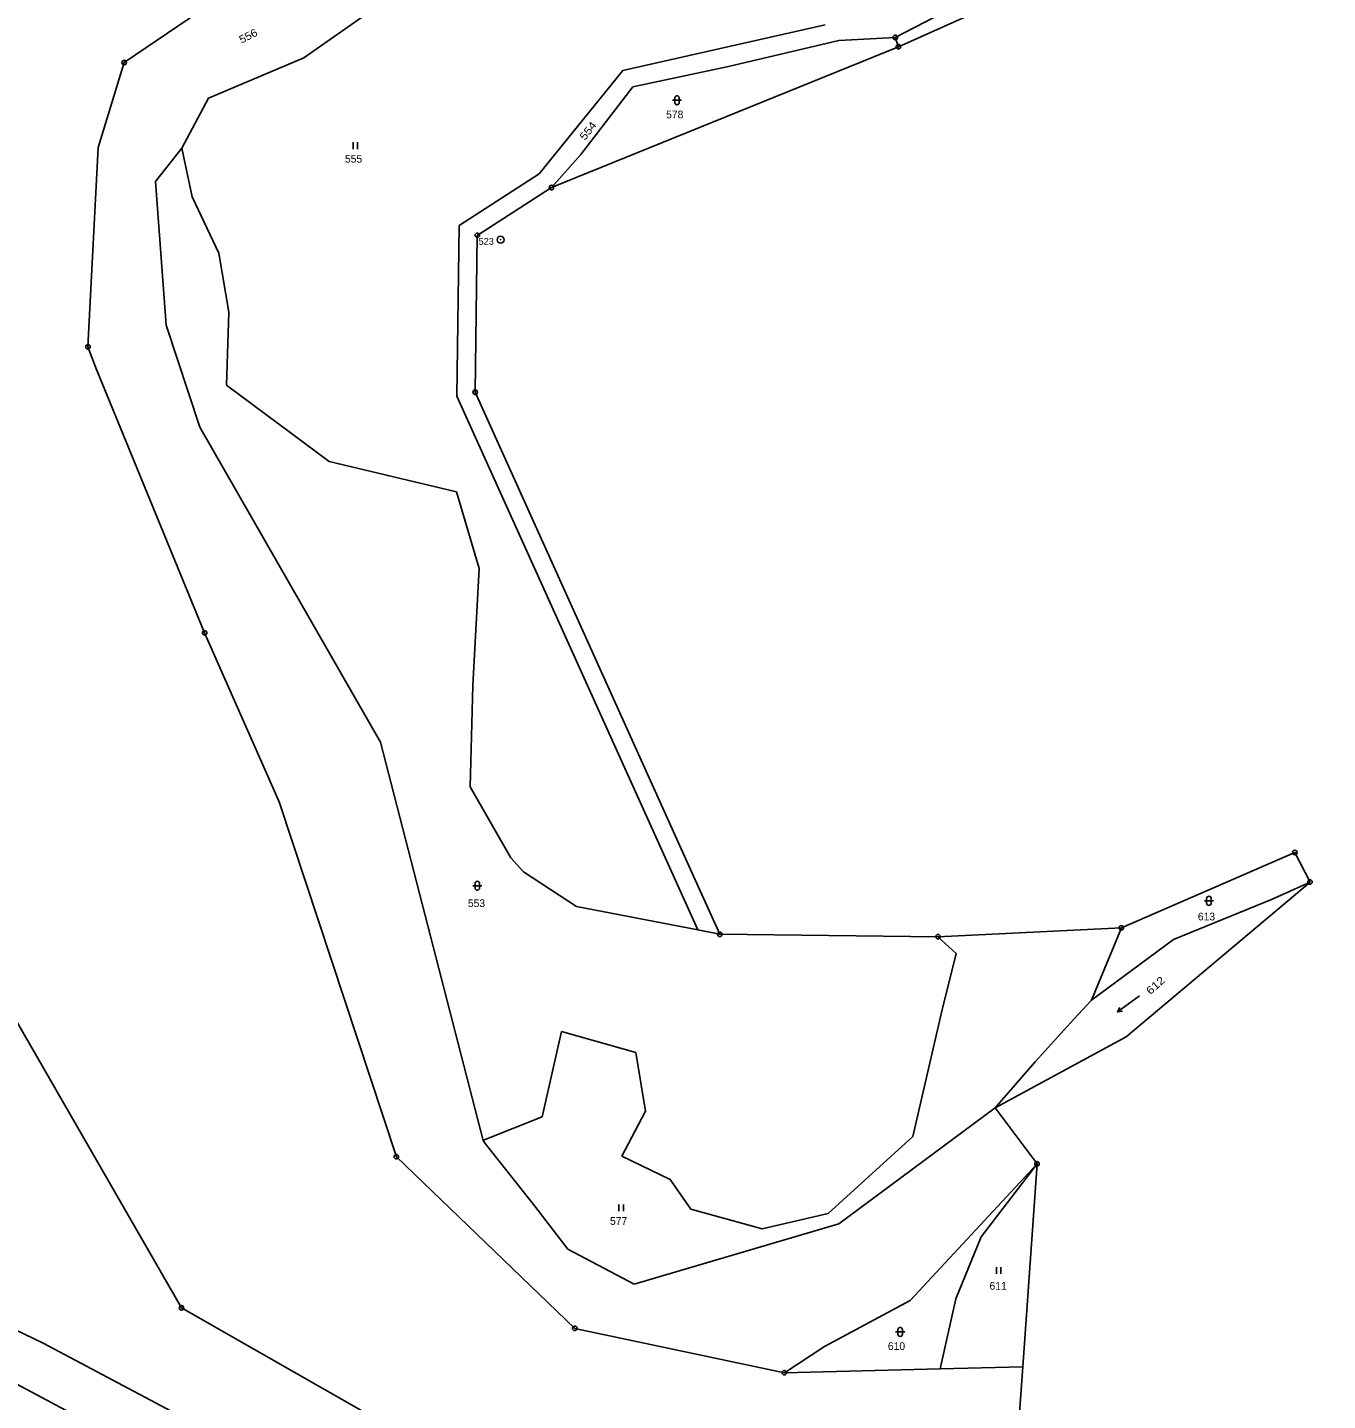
# Model space of a CAD drawing. Extents: x -719614 to -717765, y -1095834 to -1093862.
# Drawn here: x -718549.9 to -718263.5, y -1095573 to -1095270.4 of the extents above; entities that cross this region are included whole.
import ezdxf
from ezdxf.enums import TextEntityAlignment as Align

# ---------------------------------------------------------------- set-up
doc = ezdxf.new("R2010")
doc.units = 0
doc.header["$LTSCALE"] = 0.68
for name, color, linetype, lineweight in [('1', 7, 'Continuous', 25), ('3', 7, 'Continuous', 25), ('8', 7, 'Continuous', 25)]:
    doc.layers.add(name, color=color, linetype=linetype, lineweight=lineweight)
doc.layers.add('2', color=7, linetype='Continuous')

msp = doc.modelspace()

# ---------------------------------------------------------------- linework, layer by layer
at = {"layer": '1'}
for p, q in [((-718358.01, -1095274.64), (-718206.61, -1095206.83)), ((-718528.56, -1095278.15), (-718474.41, -1095241.35)), ((-718358.69, -1095272.6), (-718305.66, -1095245.1)), ((-718472.63, -1095265.67), (-718489.02, -1095277.08)), ((-718418.73, -1095279.86), (-718374.13, -1095269.82)), ((-718371.16, -1095273.26), (-718395.43, -1095279.04)), ((-718358.69, -1095272.6), (-718371.16, -1095273.26)), ((-718358.01, -1095274.64), (-718358.69, -1095272.6)), ((-718489.02, -1095277.08), (-718509.98, -1095286)), ((-718434.44, -1095305.7), (-718358.01, -1095274.64)), ((-718534.28, -1095296.85), (-718528.56, -1095278.15)), ((-718437.15, -1095302.69), (-718418.73, -1095279.86)), ((-718395.43, -1095279.04), (-718416.51, -1095283.48)), ((-718509.98, -1095286), (-718515.85, -1095297.01)), ((-718416.51, -1095283.48), (-718427.97, -1095298.42)), ((-718536.55, -1095340.82), (-718534.28, -1095296.85)), ((-718515.85, -1095297.01), (-718521.65, -1095304.39)), ((-718513.57, -1095307.72), (-718515.85, -1095297.01)), ((-718427.97, -1095298.42), (-718434.44, -1095305.7)), ((-718521.65, -1095304.39), (-718519.35, -1095336.03)), ((-718454.75, -1095314.03), (-718437.15, -1095302.69)), ((-718450.78, -1095316.23), (-718434.44, -1095305.7)), ((-718507.71, -1095320.18), (-718513.57, -1095307.72)), ((-718455.26, -1095351.64), (-718454.75, -1095314.03)), ((-718451.25, -1095350.81), (-718450.78, -1095316.23)), ((-718505.54, -1095333.16), (-718507.71, -1095320.18)), ((-718506.05, -1095349.28), (-718505.54, -1095333.16)), ((-718519.35, -1095336.03), (-718511.88, -1095358.48)), ((-718534.69, -1095345.76), (-718536.55, -1095340.82)), ((-718510.85, -1095403.84), (-718534.69, -1095345.76)), ((-718483.41, -1095366.04), (-718506.05, -1095349.28)), ((-718402.18, -1095469.27), (-718455.26, -1095351.64)), ((-718402.78, -1095458.27), (-718451.25, -1095350.81)), ((-718511.88, -1095358.48), (-718472.08, -1095427.94)), ((-718455.35, -1095372.74), (-718483.41, -1095366.04)), ((-718450.38, -1095389.64), (-718455.35, -1095372.74)), ((-718451.78, -1095415.45), (-718450.38, -1095389.64)), ((-718494.44, -1095441.1), (-718510.85, -1095403.84)), ((-718452.36, -1095437.8), (-718451.78, -1095415.45)), ((-718472.08, -1095427.94), (-718449.52, -1095515.72)), ((-718443.36, -1095453.44), (-718452.36, -1095437.8)), ((-718468.61, -1095519.3), (-718494.44, -1095441.1)), ((-718270.67, -1095452.26), (-718308.89, -1095468.86)), ((-718267.32, -1095458.76), (-718270.67, -1095452.26)), ((-718440.59, -1095456.48), (-718443.36, -1095453.44)), ((-718428.92, -1095464.17), (-718440.59, -1095456.48)), ((-718397.36, -1095470.29), (-718402.78, -1095458.27)), ((-718307.81, -1095492.88), (-718267.32, -1095458.76)), ((-718267.32, -1095458.76), (-718275.79, -1095462.62)), ((-718402.18, -1095469.27), (-718428.92, -1095464.17)), ((-718275.79, -1095462.62), (-718297.38, -1095471.45)), ((-718397.36, -1095470.29), (-718402.18, -1095469.27)), ((-718349.29, -1095470.82), (-718397.36, -1095470.29)), ((-718308.89, -1095468.86), (-718349.29, -1095470.82)), ((-718349.29, -1095470.82), (-718345.32, -1095474.48)), ((-718315.49, -1095484.77), (-718308.89, -1095468.86)), ((-718297.38, -1095471.45), (-718315.49, -1095484.77)), ((-718345.32, -1095474.48), (-718348.49, -1095487.54)), ((-718515.95, -1095552.63), (-718555.1, -1095484.57)), ((-718315.49, -1095484.77), (-718319.34, -1095489)), ((-718348.49, -1095487.54), (-718354.86, -1095514.83)), ((-718319.34, -1095489), (-718327.85, -1095498.37)), ((-718432.25, -1095491.71), (-718436.51, -1095510.5)), ((-718415.87, -1095496.37), (-718432.25, -1095491.71)), ((-718413.74, -1095509.3), (-718415.87, -1095496.37)), ((-718327.85, -1095498.37), (-718336.67, -1095508.55)), ((-718418.93, -1095519.15), (-718413.74, -1095509.3)), ((-718371.15, -1095534.11), (-718336.67, -1095508.55)), ((-718436.51, -1095510.5), (-718449.01, -1095515.52)), ((-718449.01, -1095515.52), (-718449.52, -1095515.72)), ((-718449.52, -1095515.72), (-718449.01, -1095516.43)), ((-718354.86, -1095514.83), (-718373.47, -1095531.84)), ((-718429.31, -1095557.14), (-718468.61, -1095519.3)), ((-718449.01, -1095516.43), (-718438.12, -1095530.19)), ((-718408.28, -1095524.33), (-718418.93, -1095519.15)), ((-718327.47, -1095520.86), (-718355.39, -1095551.01)), ((-718339.76, -1095536.99), (-718327.47, -1095520.86)), ((-718330.61, -1095565.64), (-718327.47, -1095520.86)), ((-718403.75, -1095530.89), (-718408.28, -1095524.33)), ((-718438.12, -1095530.19), (-718430.8, -1095539.71)), ((-718388, -1095535.17), (-718403.75, -1095530.89)), ((-718416.2, -1095547.38), (-718371.15, -1095534.11)), ((-718373.47, -1095531.84), (-718388, -1095535.17)), ((-718345.37, -1095550.63), (-718339.76, -1095536.99)), ((-718430.8, -1095539.71), (-718416.2, -1095547.38)), ((-718578.93, -1095544.76), (-718546.41, -1095560.42)), ((-718453.18, -1095588.42), (-718515.95, -1095552.63)), ((-718355.39, -1095551.01), (-718374.3, -1095561.14)), ((-718348.84, -1095566.09), (-718345.37, -1095550.63)), ((-718383.13, -1095566.91), (-718429.31, -1095557.14)), ((-718492.07, -1095601.38), (-718570.21, -1095559.91)), ((-718546.41, -1095560.42), (-718505.05, -1095582.36)), ((-718374.3, -1095561.14), (-718383.13, -1095566.91)), ((-718383.13, -1095566.91), (-718348.84, -1095566.09)), ((-718348.84, -1095566.09), (-718330.61, -1095565.64)), ((-718331.65, -1095580.47), (-718330.61, -1095565.64))]:
    msp.add_line(p, q, dxfattribs=at)
msp.add_lwpolyline([(-718327.47, -1095520.86), (-718336.67, -1095508.55), (-718307.81, -1095492.88)], dxfattribs=at)
at = {"layer": '3'}
for p, q in [((-718407.291, -1095285.951), (-718407.291, -1095286.952)), ((-718406.289, -1095286.952), (-718406.289, -1095285.951)), ((-718407.791, -1095286.451), (-718405.789, -1095286.451)), ((-718478.151, -1095297.22), (-718478.151, -1095295.72)), ((-718477.15, -1095297.22), (-718477.15, -1095295.72)), ((-718451.761, -1095459.571), (-718449.759, -1095459.571)), ((-718451.261, -1095459.071), (-718451.261, -1095460.072)), ((-718450.259, -1095460.072), (-718450.259, -1095459.071)), ((-718290.601, -1095462.911), (-718288.599, -1095462.911)), ((-718290.101, -1095462.411), (-718290.101, -1095463.412)), ((-718289.099, -1095463.412), (-718289.099, -1095462.411)), ((-718309.746, -1095487.376), (-718309.25, -1095486.396)), ((-718419.601, -1095531.34), (-718419.601, -1095529.84)), ((-718418.6, -1095531.34), (-718418.6, -1095529.84)), ((-718336.421, -1095545.15), (-718336.421, -1095543.65)), ((-718335.42, -1095545.15), (-718335.42, -1095543.65)), ((-718358.621, -1095557.921), (-718356.619, -1095557.921)), ((-718358.121, -1095557.421), (-718358.121, -1095558.422)), ((-718357.119, -1095558.422), (-718357.119, -1095557.421))]:
    msp.add_line(p, q, dxfattribs=at)
msp.add_lwpolyline([(-718304.892, -1095483.85), (-718309.746, -1095487.376), (-718308.661, -1095487.208)], dxfattribs=at)
for centre, start, end in [((-718406.79, -1095285.9509), 0, 180), ((-718406.79, -1095286.9509), 180, 359.98789), ((-718450.76, -1095459.0709), 0, 180), ((-718450.76, -1095460.0709), 180, 359.98789), ((-718289.6, -1095462.4109), 0, 180), ((-718289.6, -1095463.4109), 180, 359.98789), ((-718357.62, -1095557.4209), 0, 180), ((-718357.62, -1095558.4209), 180, 359.98789)]:
    msp.add_arc(centre, 0.5, start, end, dxfattribs=at)
at = {"layer": '8'}
for centre, radius in [((-718358.69, -1095272.5999), 0.5), ((-718358.69, -1095272.5999), 0.0303), ((-718358.01, -1095274.6399), 0.5), ((-718358.01, -1095274.6399), 0.0303), ((-718528.56, -1095278.1499), 0.5), ((-718528.56, -1095278.1499), 0.0303), ((-718434.44, -1095305.6999), 0.5), ((-718434.44, -1095305.6999), 0.0303), ((-718450.78, -1095316.2299), 0.5), ((-718450.78, -1095316.2299), 0.0303), ((-718445.64, -1095317.1898), 0.75), ((-718445.64, -1095317.1898), 0.03), ((-718536.55, -1095340.8199), 0.5), ((-718536.55, -1095340.8199), 0.0303), ((-718451.25, -1095350.8099), 0.5), ((-718451.25, -1095350.8099), 0.0303), ((-718510.85, -1095403.8399), 0.5), ((-718510.85, -1095403.8399), 0.0303), ((-718270.67, -1095452.2599), 0.5), ((-718270.67, -1095452.2599), 0.0303), ((-718267.32, -1095458.7599), 0.5), ((-718267.32, -1095458.7599), 0.0303), ((-718397.36, -1095470.2899), 0.5), ((-718397.36, -1095470.2899), 0.0303), ((-718349.29, -1095470.8199), 0.5), ((-718349.29, -1095470.8199), 0.0303), ((-718308.89, -1095468.8599), 0.5), ((-718308.89, -1095468.8599), 0.0303), ((-718468.61, -1095519.2999), 0.5), ((-718468.61, -1095519.2999), 0.0303), ((-718327.47, -1095520.8599), 0.5), ((-718327.47, -1095520.8599), 0.0303), ((-718515.95, -1095552.6299), 0.5), ((-718515.95, -1095552.6299), 0.0303), ((-718429.31, -1095557.1399), 0.5), ((-718429.31, -1095557.1399), 0.0303), ((-718383.13, -1095566.9099), 0.5), ((-718383.13, -1095566.9099), 0.0303)]:
    msp.add_circle(centre, radius, dxfattribs=at)

# ---------------------------------------------------------------- texts
at = {"layer": '2'}
for s, rotation, width, p in [('556', 27, 1.1, (-718500.8609, -1095273.0425)), ('554', 52, 1.15, (-718425.7205, -1095293.7023)), ('612', 42, 1.2, (-718300.8008, -1095482.1816))]:
    msp.add_text(s, height=1.7, rotation=rotation, dxfattribs=dict(at, width=width)).set_placement(p, align=Align.CENTER)
for s, p in [('578', (-718407.289, -1095290.432)), ('555', (-718478.039, -1095300.202)), ('553', (-718450.959, -1095464.282)), ('613', (-718290.139, -1095467.222)), ('577', (-718419.649, -1095534.322)), ('611', (-718336.039, -1095548.622)), ('610', (-718358.429, -1095561.902))]:
    msp.add_text(s, height=1.7, dxfattribs=at).set_placement(p, align=Align.CENTER)
at = {"layer": '8'}
msp.add_text('523', height=1.5, dxfattribs=at).set_placement((-718447.139, -1095318.307), align=Align.RIGHT)

doc.saveas('drawing.dxf')
